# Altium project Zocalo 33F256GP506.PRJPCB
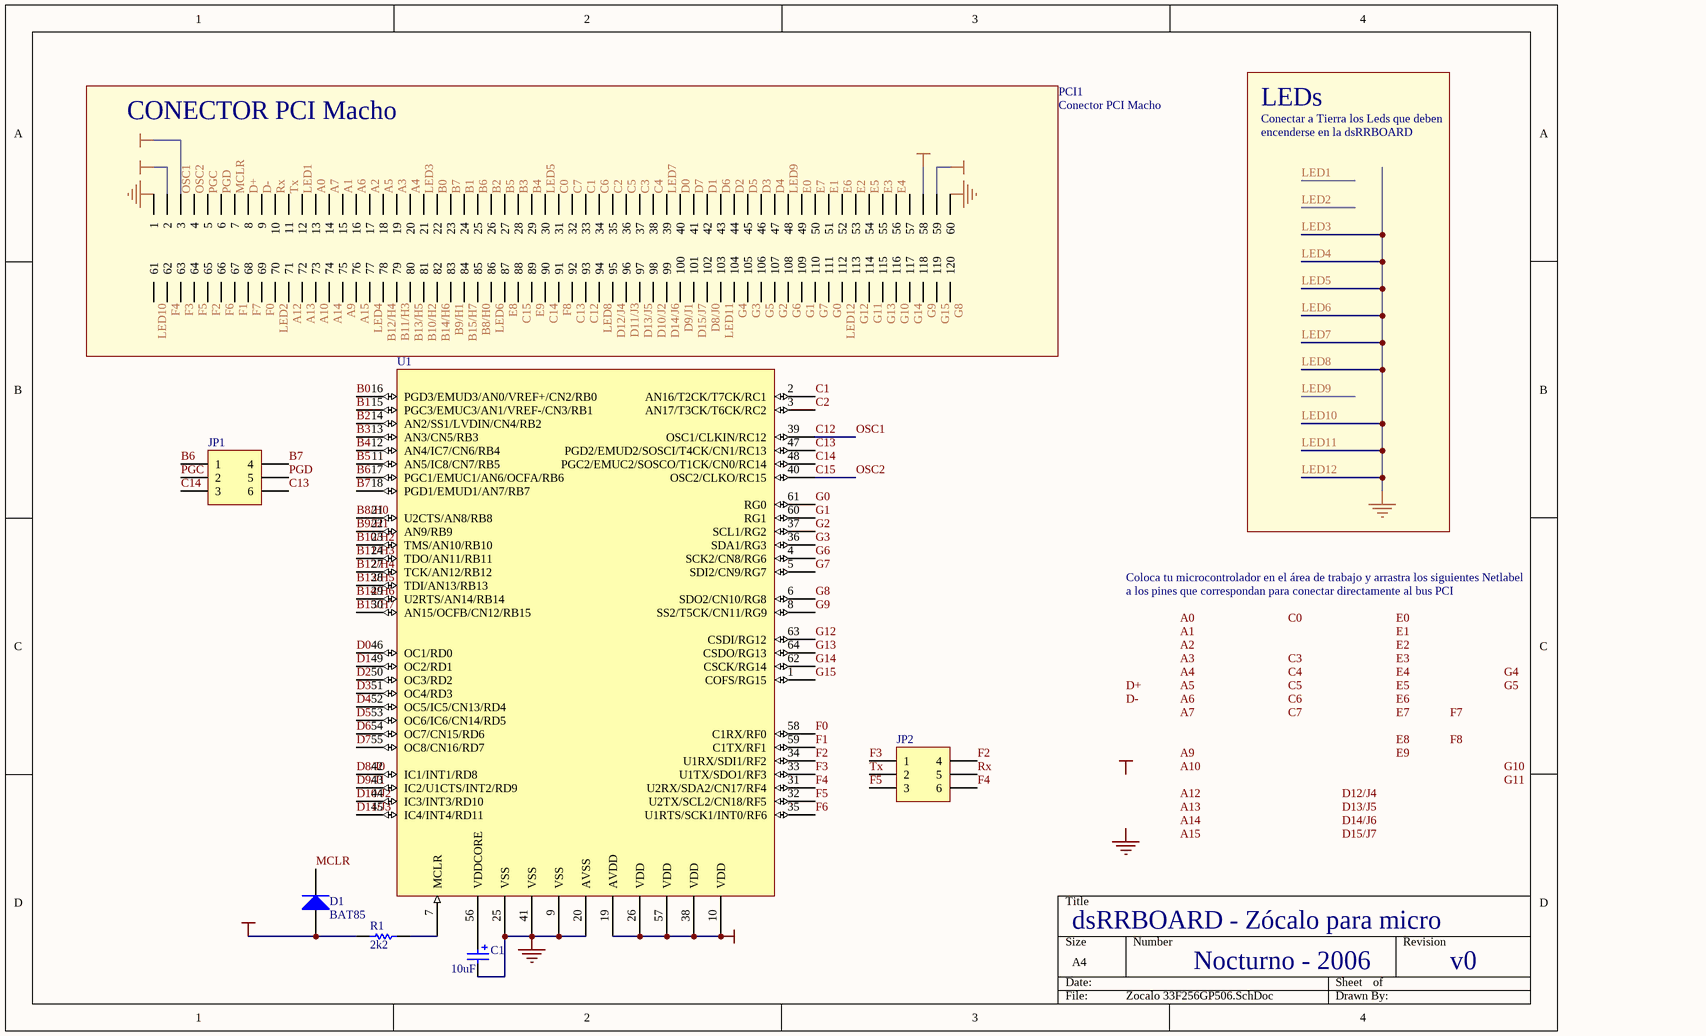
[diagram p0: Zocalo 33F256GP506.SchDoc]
1 sheet, 7 parts. Net scope: global (net labels, ports and power ports of the same name join across sheets).
Board file: Zocalo 33F256GP506.PCBDOC

## Sheet Zocalo 33F256GP506.SchDoc
size A4

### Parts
C1  value 10uF  [RB7.6-15]  (hidden comment: Cap Pol1)
D1  BAT85  [DIO7.1-3.9x1.9]
JP1  Header 3X2A  [HDR2X3_CEN]  (value not drawn)
JP2  Header 3X2A  [HDR2X3_CEN]  (value not drawn)
PCI1  Conector PCI Macho  [PCI_Macho]
R1  value 2k2  [AXIAL-0.3]  (hidden comment: Res1)
U1  o33FJ256GP506  [TQFP-64 con DIP]  (value not drawn)

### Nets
LED10: C1.2 PCI1.A1(1) PCI1.A22(22) PCI1.A31(31) PCI1.A40(40) PCI1.A60(60) PCI1.B1(61) PCI1.B17(77) PCI1.B26(86) PCI1.B34(94) PCI1.B43(103) PCI1.B52(112) U1.9(VSS) U1.20(AVSS) U1.25(VSS) U1.41(VSS)  [also labelled GND, LED11, LED12, LED3, LED4, LED5, LED6, LED7, LED8]
Vdd3.3V: D1.1(A) PCI1.A3(3) PCI1.A59(59) R1.1 U1.10(VDD) U1.19(AVDD) U1.26(VDD) U1.38(VDD) U1.57(VDD)
Vdd5V: PCI1.A2(2) PCI1.A58(58)
A0: PCI1.A14(14)
A1: PCI1.A16(16)
A2: PCI1.A18(18)
A3: PCI1.A20(20)
A4: PCI1.A21(21)
A5: PCI1.A19(19)
A6: PCI1.A17(17)
A7: PCI1.A15(15)
A9: PCI1.B15(75)
A10: PCI1.B13(73)
A12: PCI1.B11(71)
A13: PCI1.B12(72)
A14: PCI1.B14(74)
A15: PCI1.B16(76)
B0: PCI1.A23(23) U1.16(PGD3/EMUD3/AN0/VREF+/CN2/RB0)
B1: PCI1.A25(25) U1.15(PGC3/EMUC3/AN1/VREF-/CN3/RB1)
B2: PCI1.A27(27) U1.14(AN2/SS1/LVDIN/CN4/RB2)
B3: PCI1.A29(29) U1.13(AN3/CN5/RB3)
B4: PCI1.A30(30) U1.12(AN4/IC7/CN6/RB4)
B5: PCI1.A28(28) U1.11(AN5/IC8/CN7/RB5)
B6: JP1.1 PCI1.A26(26) U1.17(PGC1/EMUC1/AN6/OCFA/RB6)
B7: JP1.4 PCI1.A24(24) U1.18(PGD1/EMUD1/AN7/RB7)
B8/H0: PCI1.B25(85) U1.21(U2CTS/AN8/RB8)
B9/H1: PCI1.B23(83) U1.22(AN9/RB9)
B10/H2: PCI1.B21(81) U1.23(TMS/AN10/RB10)
B11/H3: PCI1.B19(79) U1.24(TDO/AN11/RB11)
B12/H4: PCI1.B18(78) U1.27(TCK/AN12/RB12)
B13/H5: PCI1.B20(80) U1.28(TDI/AN13/RB13)
B14/H6: PCI1.B22(82) U1.29(U2RTS/AN14/RB14)
B15/H7: PCI1.B24(84) U1.30(AN15/OCFB/CN12/RB15)
C0: PCI1.A32(32)
C1: PCI1.A34(34) U1.2(AN16/T2CK/T7CK/RC1)
C2: PCI1.A36(36) U1.3(AN17/T3CK/T6CK/RC2)
C3: PCI1.A38(38)
C4: PCI1.A39(39)
C5: PCI1.A37(37)
C6: PCI1.A35(35)
C7: PCI1.A33(33)
C12: PCI1.A4(4) PCI1.B33(93) U1.39(OSC1/CLKIN/RC12)  [also labelled OSC1]
C13: JP1.6 PCI1.B32(92) U1.47(PGD2/EMUD2/SOSCI/T4CK/CN1/RC13)
C14: JP1.3 PCI1.B30(90) U1.48(PGC2/EMUC2/SOSCO/T1CK/CN0/RC14)
C15: PCI1.A5(5) PCI1.B28(88) U1.40(OSC2/CLKO/RC15)  [also labelled OSC2]
D0: PCI1.A41(41) U1.46(OC1/RD0)
D1: PCI1.A43(43) U1.49(OC2/RD1)
D2: PCI1.A45(45) U1.50(OC3/RD2)
D3: PCI1.A47(47) U1.51(OC4/RD3)
D4: PCI1.A48(48) U1.52(OC5/IC5/CN13/RD4)
D5: PCI1.A46(46) U1.53(OC6/IC6/CN14/RD5)
D6: PCI1.A44(44) U1.54(OC7/CN15/RD6)
D7: PCI1.A42(42) U1.55(OC8/CN16/RD7)
D8/J0: PCI1.B42(102) U1.42(IC1/INT1/RD8)
D9/J1: PCI1.B40(100) U1.43(IC2/U1CTS/INT2/RD9)
D10/J2: PCI1.B38(98) U1.44(IC3/INT3/RD10)
D11/J3: PCI1.B36(96) U1.45(IC4/INT4/RD11)
D12/J4: PCI1.B35(95)
D13/J5: PCI1.B37(97)
D14/J6: PCI1.B39(99)
D15/J7: PCI1.B41(101)
D+: PCI1.A9(9)
D-: PCI1.A10(10)
E0: PCI1.A50(50)
E1: PCI1.A52(52)
E2: PCI1.A54(54)
E3: PCI1.A56(56)
E4: PCI1.A57(57)
E5: PCI1.A55(55)
E6: PCI1.A53(53)
E7: PCI1.A51(51)
E8: PCI1.B27(87)
E9: PCI1.B29(89)
F0: PCI1.B9(69) U1.58(C1RX/RF0)
F1: PCI1.B7(67) U1.59(C1TX/RF1)
F2: JP2.4 PCI1.B5(65) U1.34(U1RX/SDI1/RF2)
F3: JP2.1 PCI1.B3(63) U1.33(U1TX/SDO1/RF3)
F4: JP2.6 PCI1.B2(62) U1.31(U2RX/SDA2/CN17/RF4)
F5: JP2.3 PCI1.B4(64) U1.32(U2TX/SCL2/CN18/RF5)
F6: PCI1.B6(66) U1.35(U1RTS/SCK1/INT0/RF6)
F7: PCI1.B8(68)
F8: PCI1.B31(91)
G0: PCI1.B51(111) U1.61(RG0)
G1: PCI1.B49(109) U1.60(RG1)
G2: PCI1.B47(107) U1.37(SCL1/RG2)
G3: PCI1.B45(105) U1.36(SDA1/RG3)
G4: PCI1.B44(104)
G5: PCI1.B46(106)
G6: PCI1.B48(108) U1.4(SCK2/CN8/RG6)
G7: PCI1.B50(110) U1.5(SDI2/CN9/RG7)
G8: PCI1.B60(120) U1.6(SDO2/CN10/RG8)
G9: PCI1.B58(118) U1.8(SS2/T5CK/CN11/RG9)
G10: PCI1.B56(116)
G11: PCI1.B54(114)
G12: PCI1.B53(113) U1.63(CSDI/RG12)
G13: PCI1.B55(115) U1.64(CSDO/RG13)
G14: PCI1.B57(117) U1.62(CSCK/RG14)
G15: PCI1.B59(119) U1.1(COFS/RG15)
LED1: PCI1.A13(13)
LED2: PCI1.B10(70)
LED9: PCI1.A49(49)
MCLR: D1.2(K) PCI1.A8(8)
PGC: JP1.2 PCI1.A6(6)
PGD: JP1.5 PCI1.A7(7)
Rx: JP2.5 PCI1.A11(11)
Tx: JP2.2 PCI1.A12(12)
NetC1_1: C1.1 U1.56(VDDCORE)
NetR1_2: R1.2 U1.7(MCLR)

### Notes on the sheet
- LEDs
- encenderse en la dsRRBOARD
- Conectar a Tierra los Leds que deben
- Coloca tu microcontrolador en el área de trabajo y arrastra los siguientes Netlabel
- a los pines que correspondan para conectar directamente al bus PCI
- dsRRBOARD - Zócalo para micro
- Nocturno - 2006
- v0
- Labels drawn without touching a wire or pin: A0, A1, A2, A3, A4, A5, A6, A7, A9, A10, A12, A13, A14, A15, C0, C3, C4, C5, C6, C7, D12/J4, D13/J5, D14/J6, D15/J7, D+, D-, E0, E1, E2, E3, E4, E5, E6, E7, E8, E9, F7, F8, G4, G5, G10, G11, GND, Vdd5V

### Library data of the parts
C1 = Cap Pol1: Polarized Capacitor (Radial)
D1 = Diode 1N4148: High Conductance Fast Diode; Revision 1: 11-Jul-2000: SIM Model Added.; Revision 2: 17-Jul-2002: Re-released for DXP Platform.; Code - JEDEC: DO-204-AH
JP1 JP2 = Header 3X2A: Header, 3-Pin, Dual row
R1 = Res1: Resistor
